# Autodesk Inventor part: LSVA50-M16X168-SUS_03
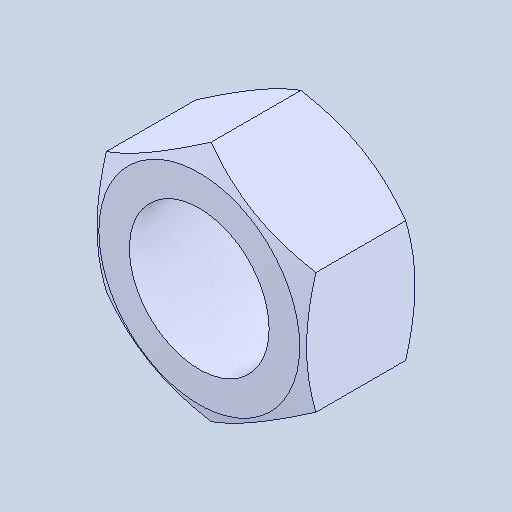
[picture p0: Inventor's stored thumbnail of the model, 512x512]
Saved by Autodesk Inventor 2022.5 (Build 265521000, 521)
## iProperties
Created: 2024-08
Part Number: LSVA50-M16X168-SUS_03
Material: 一般
Document SubType Name: Modeling
Designer: ImaoCorp
Density: 1 g/cm^3
Appearance: 既定
Author: ImaoCorp
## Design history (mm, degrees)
feature "LSVA50-M16X168-SUS_03"
node "ソリッド1"
